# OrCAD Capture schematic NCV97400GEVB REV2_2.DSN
size B; title: NCV97400 Evaluation Board Schematic; rev: 2_2; note: Main Page
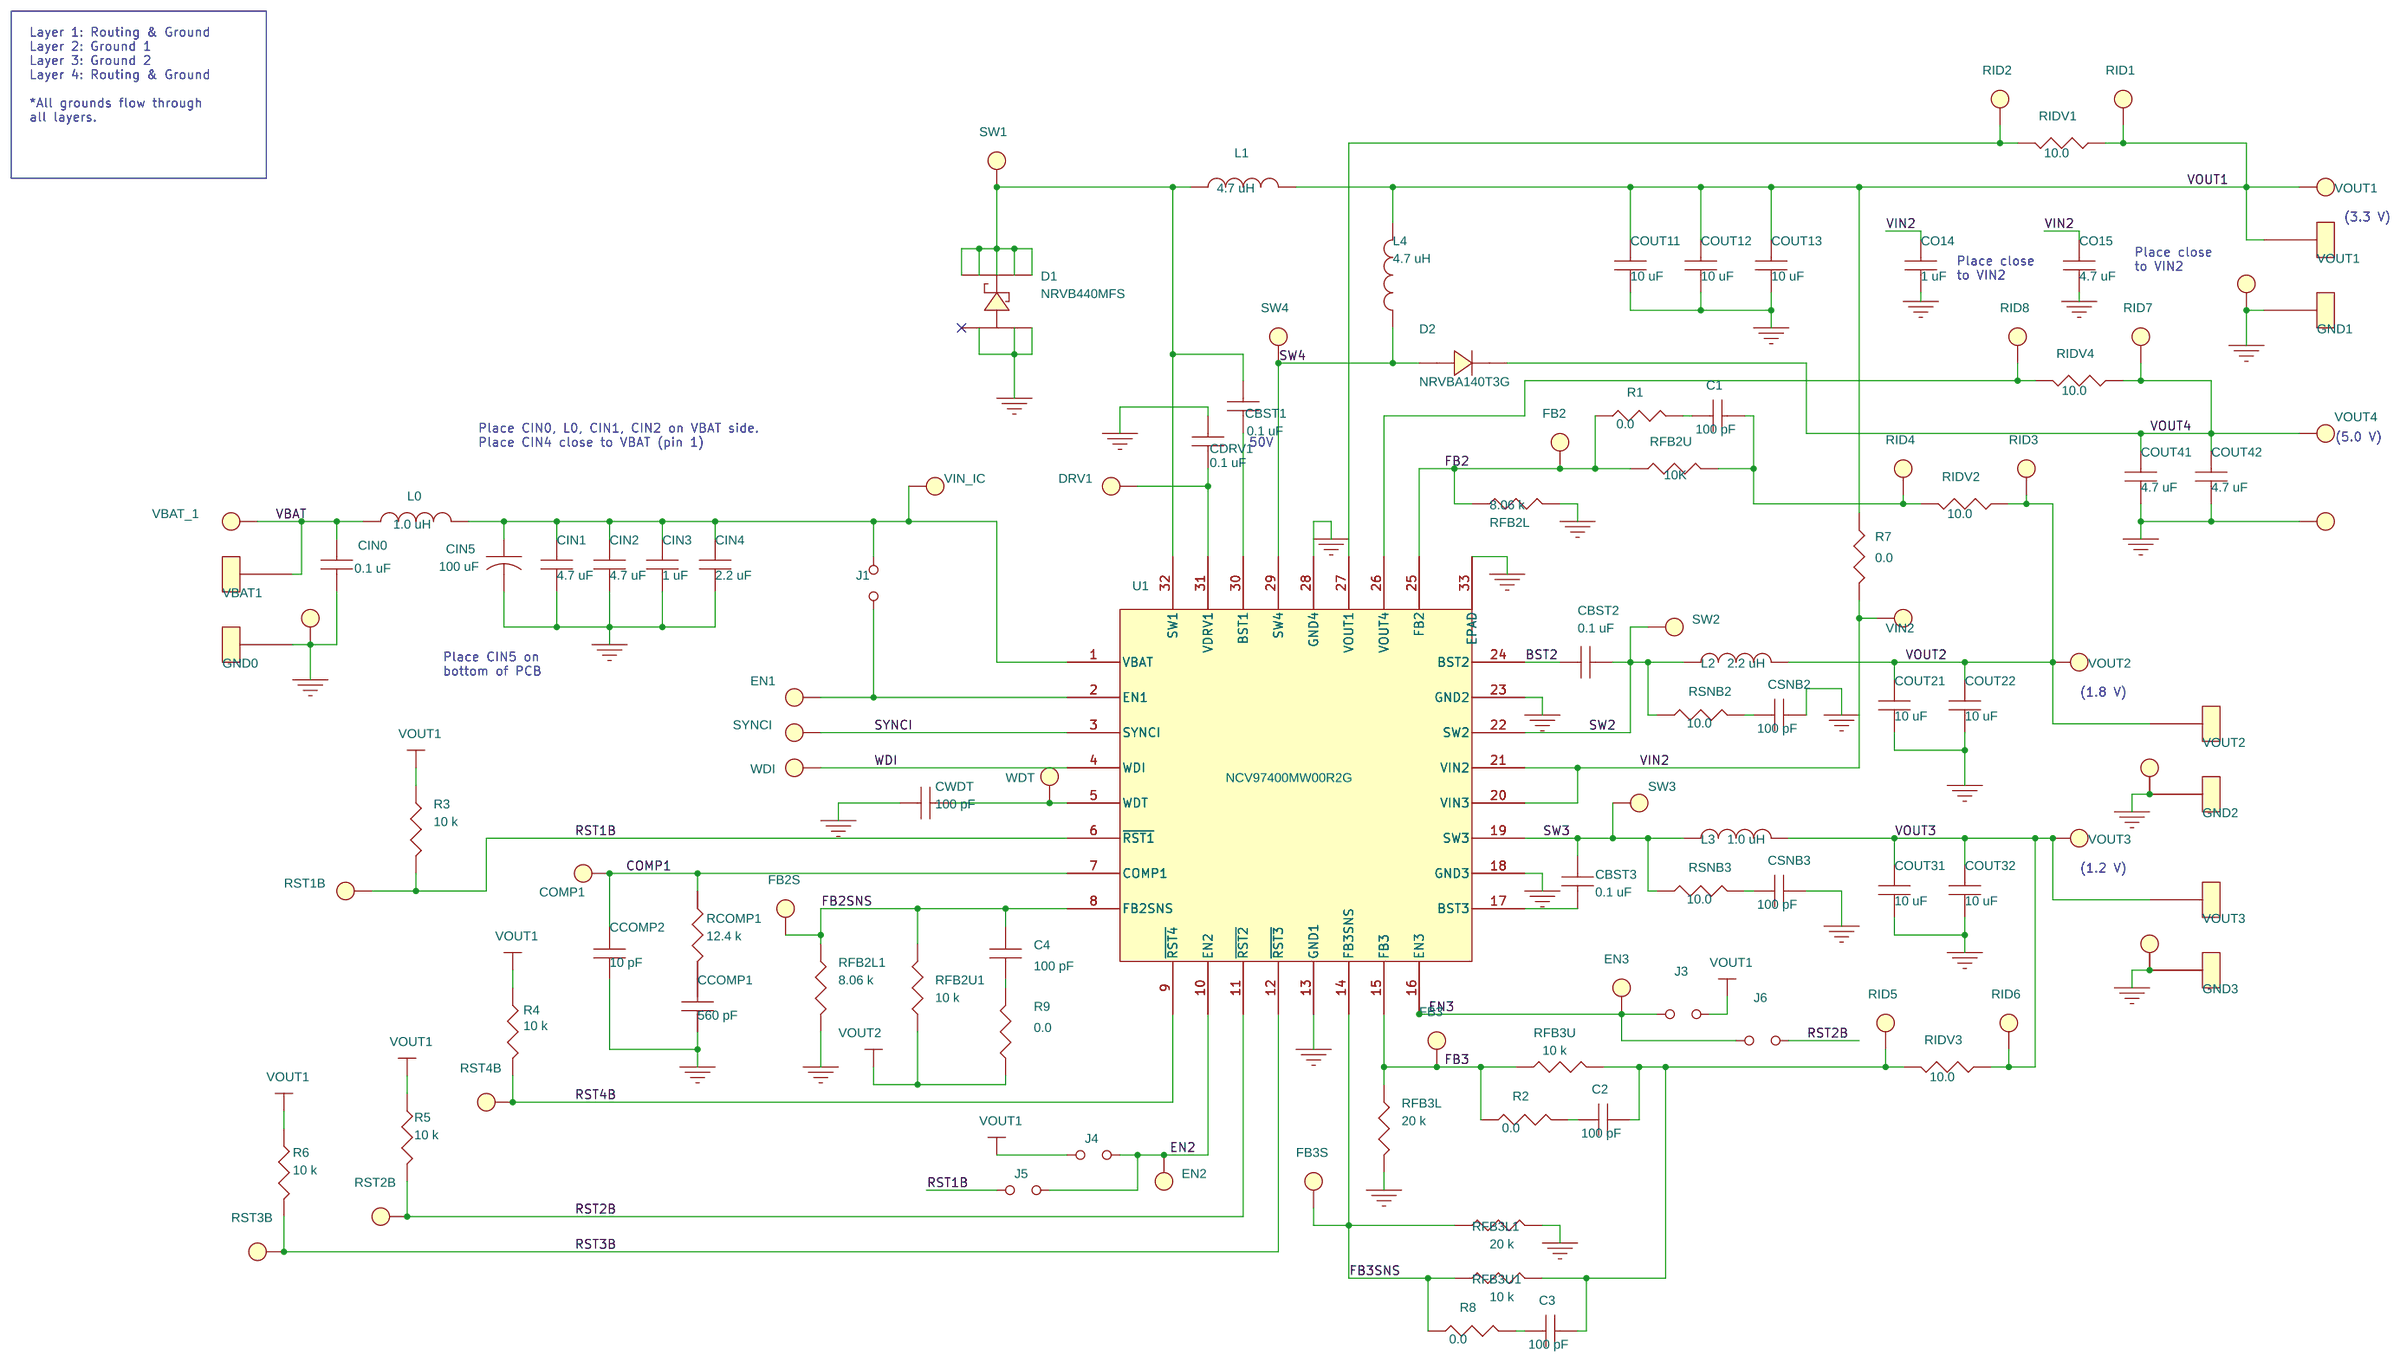
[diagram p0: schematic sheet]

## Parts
C1  100 pF  [0603]
C2  100 pF  [0603]
C3  100 pF  [0603]
C4  100 pF  [0603]
CBST1  0.1 uF  [0603]
CBST2  0.1 uF  [0603]
CBST3  0.1 uF  [0603]
CCOMP1  560 pF  [0603]
CCOMP2  10 pF  [0603]
CDRV1  0.1 uF  [0603]
CIN0  0.1 uF  [1206]
CIN1  4.7 uF  [1206]
CIN2  4.7 uF  [1206]
CIN3  1 uF  [1206]
CIN4  2.2 uF  [1206]
CIN5  100 uF  [FK_V_E]
CO14  1 uF  [0603]
CO15  4.7 uF  [0805]
COMP1  COMP1  [SMALLTP]
COUT11  10 uF  [1206]
COUT12  10 uF  [1206]
COUT13  10 uF  [1206]
COUT21  10 uF  [1206]
COUT22  10 uF  [1206]
COUT31  10 uF  [1206]
COUT32  10 uF  [1206]
COUT41  4.7 uF  [0805]
COUT42  4.7 uF  [0805]
CSNB2  100 pF  [0603]
CSNB3  100 pF  [0603]
CWDT  100 pF  [0603]
D1  NRVB440MFS  [MBR340MFS]
D2  NRVBA140T3G  [SMA_DIODE]
DRV1  DRV1  [SMALLTP]
EN1  EN1  [TP]
EN2  EN2  [TP]
EN3  EN3  [TP]
FB2  FB2  [SMALLTP]
FB2S  FB2S  [SMALLTP]
FB3  FB3  [SMALLTP]
FB3S  FB3S  [SMALLTP]
GND0  PGND1  [BANANA]
GND1  PGND1  [BANANA]
GND2  PGND2  [BANANA]
GND3  PGND3  [BANANA]
J1  JUMPER  [JMP]
J3  JUMPER  [JMP]
J4  JUMPER  [JMP]
J5  JUMPER  [JMP]
J6  JUMPER  [JMP]
L0  1.0 uH  [XAL4030-472]
L1  4.7 uH  [XAL4030-472]
L2  2.2 uH  [XAL4030-472]
L3  1.0 uH  [XAL4030-472]
L4  4.7 uH  [XFL3010]
PGND1_1  PGND1  [TP]
PGND1_2  PGND1  [TP]
PGND2_1  PGND2  [TP]
PGND3_1  PGND3  [TP]
PGND4_1  PGND4  [TP]
R1  0.0  [0603]
R2  0.0  [0603]
R3  10 k  [0603]
R4  10 k  [0603]
R5  10 k  [0603]
R6  10 k  [0603]
R7  0.0  [1206]
R8  0.0  [0603]
R9  0.0  [0603]
RCOMP1  12.4 k  [0603]
RFB2L  8.06 k  [0603]
RFB2L1  8.06 k  [0603]
RFB2U  10K  [0603]
RFB2U1  10 k  [0603]
RFB3L  20 k  [0603]
RFB3L1  20 k  [0603]
RFB3U  10 k  [0603]
RFB3U1  10 k  [0603]
RID1  RID1  [SMALLTP]
RID2  RID2  [SMALLTP]
RID3  RID3  [SMALLTP]
RID4  RID4  [SMALLTP]
RID5  RID5  [SMALLTP]
RID6  RID6  [SMALLTP]
RID7  RID7  [SMALLTP]
RID8  RID8  [SMALLTP]
RIDV1  10.0  [0603]
RIDV2  10.0  [0603]
RIDV3  10.0  [0603]
RIDV4  10.0  [0603]
RSNB2  10.0  [0603]
RSNB3  10.0  [0603]
RST1B  RST1B  [TP]
RST2B  RST2B  [TP]
RST3B  RST3B  [TP]
RST4B  RST4B  [TP]
SW1  SW1  [TP]
SW2  SW2  [TP]
SW3  SW3  [TP]
SW4  SW4  [TP]
SYNCI  SYNCI  [TP]
U1  NCV97400MW00R2G  [QFN32]
VBAT  VBAT_1  [TP]
VBAT1  VBAT  [BANANA]
VIN2  VIN2  [TP]
VIND  VIN_IC  [SMALLTP]
VOUT1  VOUT1  [BANANA]
VOUT1_1  VOUT1  [TP]
VOUT2  VOUT2  [BANANA]
VOUT2_1  VOUT2  [TP]
VOUT3  VOUT3  [BANANA]
VOUT3_1  VOUT3  [TP]
VOUT4  VOUT4  [TP]
WDI  WDI  [TP]
WDT  WDT  [SMALLTP]

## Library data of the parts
C1-C4 CBST1-CBST3 CDRV1 CSNB2 CSNB3 = CAPACITOR_NON-POL: Part Number: GCM1885C1H101JA16D
CCOMP1 = CAPACITOR_NON-POL: Part Number: GCM1885C1H561JA16D
CCOMP2 = CAPACITOR_NON-POL: Part Number: GCM1885C1H100JA16D
CIN0-CIN2 = CAPACITOR_NON-POL: Part Number: C3216X7R1H475K160AC
CIN3 = CAPACITOR_NON-POL: Part Number: GCM31MR71H105KA55L
CIN4 = CAPACITOR_NON-POL: Part Number: GCM31CR71H225KA55L
CIN5 = CAP: Part Number: EMZA500ADA101MHA0G
CO14 = CAPACITOR_NON-POL: Part Number: GCM188R71C105KA64D
CO15 = CAPACITOR_NON-POL: Part Number: CGA4J3X7R1C475K125AB
COMP1 DRV1 FB2 FB2S FB3 FB3S RID1-RID8 VIND WDI WDT = T_POINT_R: Part Number: 3128-2-00-15-00-00-08-0
COUT11-COUT13 COUT21 COUT22 COUT31 COUT32 COUT41 COUT42 = CAPACITOR_NON-POL: Part Number: GCM31CR71A106KA64L
CWDT = CAPACITOR_NON-POL: Part Number: GCM188R71C474KA55D
D1 = DIODE_SCHOTTKY_3
D2 = DIODE_0
EN1-EN3 PGND1_1 PGND1_2 PGND2_1 PGND3_1 PGND4_1 RST1B RST2B RST3B RST4B SW1-SW4 SYNCI VBAT VIN2 VOUT1_1 VOUT2_1 VOUT3_1 VOUT4 = T_POINT_R: Part Number: K24C/M
GND0-GND3 VBAT1 VOUT1-VOUT3 = TEST_POINT: Part Number: 108-0740-001
J1 J3-J6 = JUMPER_0: Part Number: 22-28-4023
L0 L3 = INDUCTOR: Part Number: XAL4020-102ME
L1 = INDUCTOR: Part Number: XAL4030-472ME
L2 = INDUCTOR: Part Number: XAL4020-222ME
L4 = INDUCTOR: Part Number: XFL3010-472ME
R1 R2 R8 R9 = RESISTOR: Part Number: CRCW06030000Z0EA
R3-R6 RFB2U RFB2U1 RFB3U RFB3U1 = RESISTOR: Part Number: CRCW060310K0FKEA
R7 = RESISTOR: Part Number: CRCW12060000Z0EA
RCOMP1 = RESISTOR: Part Number: CRCW060312K4FKEA
RFB2L RFB2L1 = RESISTOR: Part Number: CRCW06035K76FKEA
RFB3L RFB3L1 = RESISTOR: Part Number: Open
RIDV1-RIDV4 RSNB2 RSNB3 = RESISTOR: Part Number: CRCW06031R00FKEA
U1 = NCV97310_0

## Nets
GND: CCOMP1.1 CCOMP2.1 CDRV1.1 CIN0.2 CIN1.2 CIN2.2 CIN3.2 CIN4.2 CIN5.2 CO14.2 CO15.2 COUT11.2 COUT12.2 COUT13.2 COUT21.2 COUT22.2 COUT31.2 COUT32.2 COUT41.2 COUT42.2 CSNB2.2 CSNB3.2 CWDT.1 D1.1(ANODE) D1.2(ANODE) D1.3(ANODE) GND0.1 GND1.1 GND2.1 GND3.1 PGND1_1.1(TP) PGND1_2.1(TP) PGND2_1.1(TP) PGND3_1.1(TP) PGND4_1.1(TP) RFB2L.2 RFB2L1.2 RFB3L.2 RFB3L1.2 U1.13(GND1) U1.18(GND3) U1.23(GND2) U1.28(GND4) U1.33(EPAD)
VBAT: CIN0.1 L0.1 VBAT.1(TP) VBAT1.1
VIN2: CO14.1 CO15.1 R7.2 U1.20(VIN3) U1.21(VIN2) VIN2.1(TP)
BST2: CBST2.1 U1.24(BST2)
COMP1: CCOMP2.2 COMP1.1(TP) RCOMP1.1 U1.7(COMP1)
EN2: EN2.1(TP) J4.2 J5.2 U1.10(EN2)
EN3: EN3.1(TP) J3.1 J6.1 U1.16(EN3)
FB2: FB2.1(TP) R1.1 RFB2L.1 RFB2U.1 U1.25(FB2)
FB2SNS: C4.2 FB2S.1(TP) RFB2L1.1 RFB2U1.2 U1.8(FB2SNS)
FB3: FB3.1(TP) R2.1 RFB3L.1 RFB3U.1 U1.15(FB3)
FB3SNS: FB3S.1(TP) R8.1 RFB3L1.1 RFB3U1.1 U1.14(FB3SNS)
RST1B: J5.1 R3.2 RST1B.1(TP) U1.6(~{RST1})
RST2B: J6.2 R5.2 RST2B.1(TP) U1.11(~{RST2})
RST3B: R6.2 RST3B.1(TP) U1.12(~{RST3})
RST4B: R4.2 RST4B.1(TP) U1.9(~{RST4})
SW2: CBST2.2 L2.1 RSNB2.1 SW2.1(TP) U1.22(SW2)
SW3: CBST3.1 L3.1 RSNB3.1 SW3.1(TP) U1.19(SW3)
SW4: D2.1(A) L4.1 SW4.1(TP) U1.29(SW4)
SYNCI: SYNCI.1(TP) U1.3(SYNCI)
VOUT1: COUT11.1 COUT12.1 COUT13.1 J3.2 J4.1 L1.2 L4.2 R3.1 R4.1 R5.1 R6.1 R7.1 RID1.1(TP) RIDV1.1 VOUT1.1 VOUT1_1.1(TP)
VOUT2: COUT21.1 COUT22.1 L2.2 R9.1 RFB2U1.1 RID3.1(TP) RIDV2.1 VOUT2.1 VOUT2_1.1(TP)
VOUT3: COUT31.1 COUT32.1 L3.2 RID6.1(TP) RIDV3.1 VOUT3.1 VOUT3_1.1(TP)
VOUT4: COUT41.1 COUT42.1 D2.2(K) RID7.1(TP) RIDV4.1 VOUT4.1(TP)
WDI: U1.4(WDI) WDI.1(TP)
N1409436: CBST1.1 D1.5(CATHODE) D1.6(CATHODE) D1.7(CATHODE) D1.8(CATHODE) D1.9(CATHODE) L1.1 SW1.1(TP) U1.32(SW1)
N1409796: CBST1.2 U1.30(BST1)
N1410000: CIN1.1 CIN2.1 CIN3.1 CIN4.1 CIN5.1 J1.2 L0.2 U1.1(VBAT) VIND.1(TP)
N1410048: CDRV1.2 DRV1.1(TP) U1.31(VDRV1)
N1410138: CWDT.2 U1.5(WDT) WDT.1(TP)
N1410322: C1.2 RFB2U.2 RID4.1(TP) RIDV2.2
N1410530: CBST3.2 U1.17(BST3)
N1410736: C1.1 R1.2
N1410740: C2.1 R2.2
N1410786: C2.2 C3.2 RFB3U.2 RFB3U1.2 RID5.1(TP) RIDV3.2
N1410794: CSNB2.1 RSNB2.2
N1410798: CSNB3.1 RSNB3.2
N1419572: EN1.1(TP) J1.1 U1.2(EN1)
N1444961: RID8.1(TP) RIDV4.2 U1.26(VOUT4)
N1449876: C3.1 R8.2
N1450005: C4.1 R9.2
N1457415: RID2.1(TP) RIDV1.2 U1.27(VOUT1)
N1461090: CCOMP1.2 RCOMP1.2

Not connected (* = marked no-connect by the designer): D1 4(NC)*

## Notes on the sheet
- Layer 1: Routing & Ground
  Layer 2: Ground 1
  Layer 3: Ground 2
  Layer 4: Routing & Ground
  *All grounds flow through
  all layers.
- (3.3 V)
- Place close
  to VIN2
- Place close
  to VIN2
- Place CIN0, L0, CIN1, CIN2 on VBAT side.
  Place CIN4 close to VBAT (pin 1)
- (5.0 V)
- 50V
- Place CIN5 on
  bottom of PCB
- (1.8 V)
- (1.2 V)
